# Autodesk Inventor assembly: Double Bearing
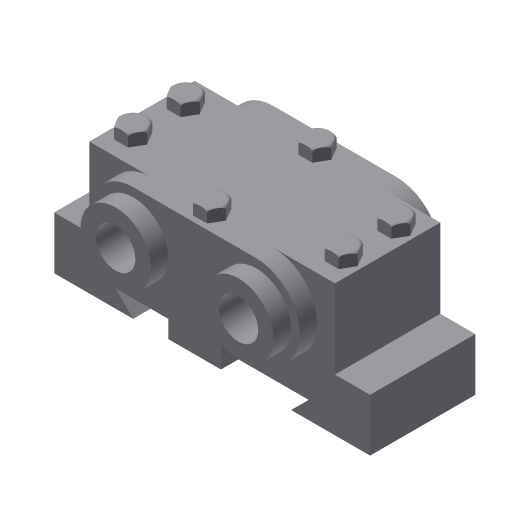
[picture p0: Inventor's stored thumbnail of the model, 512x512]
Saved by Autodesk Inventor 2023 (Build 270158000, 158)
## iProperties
Shininess: 64.0
Length Units: 11269
Angle Units: 11279
Time Units: 11290
Mass Units: 11283
Length Display Precision: 3
Angle Display Precision: 2
Created: 2002-02
Part Number: Double Bearing
Document SubType Name: Assembly
Designer: ***
Density: 0.0
Volumn: 0.0
Area: 0.0
PropertySet Name: Model Information
Control State: 0
Master: False
Checked Out: False
Author: ***
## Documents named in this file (5)
- D:\PROJECTS\Project 2022\Autodesk Inventor For Professional 2023\RESOURCES INVENTOR 2023\RESOURCES INVENTOR 2023\Inventor_2023_tut\Inventor_2023_tut\c12_Inv_2023_tut\c12_Inv_tut_2023\c12_tut02_inv\Double Bearing.iam
- D:\PROJECTS\Project 2022\Autodesk Inventor For Professional 2023\RESOURCES INVENTOR 2023\RESOURCES INVENTOR 2023\Inventor_2023_tut\Inventor_2023_tut\c12_Inv_2023_tut\c12_Inv_tut_2023\c12_tut02_inv\Base.ipt
- D:\PROJECTS\Project 2022\Autodesk Inventor For Professional 2023\RESOURCES INVENTOR 2023\RESOURCES INVENTOR 2023\Inventor_2023_tut\Inventor_2023_tut\c12_Inv_2023_tut\c12_Inv_tut_2023\c12_tut02_inv\Cap.ipt
- D:\PROJECTS\Project 2022\Autodesk Inventor For Professional 2023\RESOURCES INVENTOR 2023\RESOURCES INVENTOR 2023\Inventor_2023_tut\Inventor_2023_tut\c12_Inv_2023_tut\c12_Inv_tut_2023\c12_tut02_inv\Bushing.ipt
- D:\PROJECTS\Project 2022\Autodesk Inventor For Professional 2023\RESOURCES INVENTOR 2023\RESOURCES INVENTOR 2023\Inventor_2023_tut\Inventor_2023_tut\c12_Inv_2023_tut\c12_Inv_tut_2023\c12_tut02_inv\Bolt.ipt
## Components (10 placed, 4 different names)
1. Base:1 — Insert:1, Insert:2
2. Cap:1 — Insert:1, Insert:2, Insert:3, Insert:4, Insert:5, Insert:6
3. Bushing:1 — Insert:3
4. Bushing:2 — Insert:4
5. Bolt:1 — Insert:5
6. Bolt:6
7. Bolt:7
8. Bolt:8
9. Bolt:5 — Insert:6
10. Bolt:9
## Component patterns: Component Pattern 1 (4 elements), Component Pattern 2 (2 elements)
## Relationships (6: Insert 6)
- Insert:1: Base:1 ↔ Cap:1
- Insert:2: Base:1 ↔ Cap:1
- Insert:3: Cap:1 ↔ Bushing:1
- Insert:4: Cap:1 ↔ Bushing:2
- Insert:5: Cap:1 ↔ Bolt:1
- Insert:6: Cap:1 ↔ Bolt:5
